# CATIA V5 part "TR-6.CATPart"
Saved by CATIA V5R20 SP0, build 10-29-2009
Part number: _TR-6
Definition: NONE
Nomenclature: _TR-6
Source: Unknown
Description: PART-_TR-6-DESC
Bounding box of the stored display mesh (mm): x 0 to 7.5, y -3.65 to 3.65, z -3.65 to 3.65
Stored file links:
  C:\Users\Utente\Desktop\IO LAVORO\3D X SITO CF\X SITO\PLASTICA\TR\TR-6.CATPart
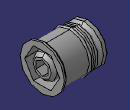
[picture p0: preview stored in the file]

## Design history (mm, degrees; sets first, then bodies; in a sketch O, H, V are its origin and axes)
Body1 "_TR-6" (main body)
  Solid1: solid without history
